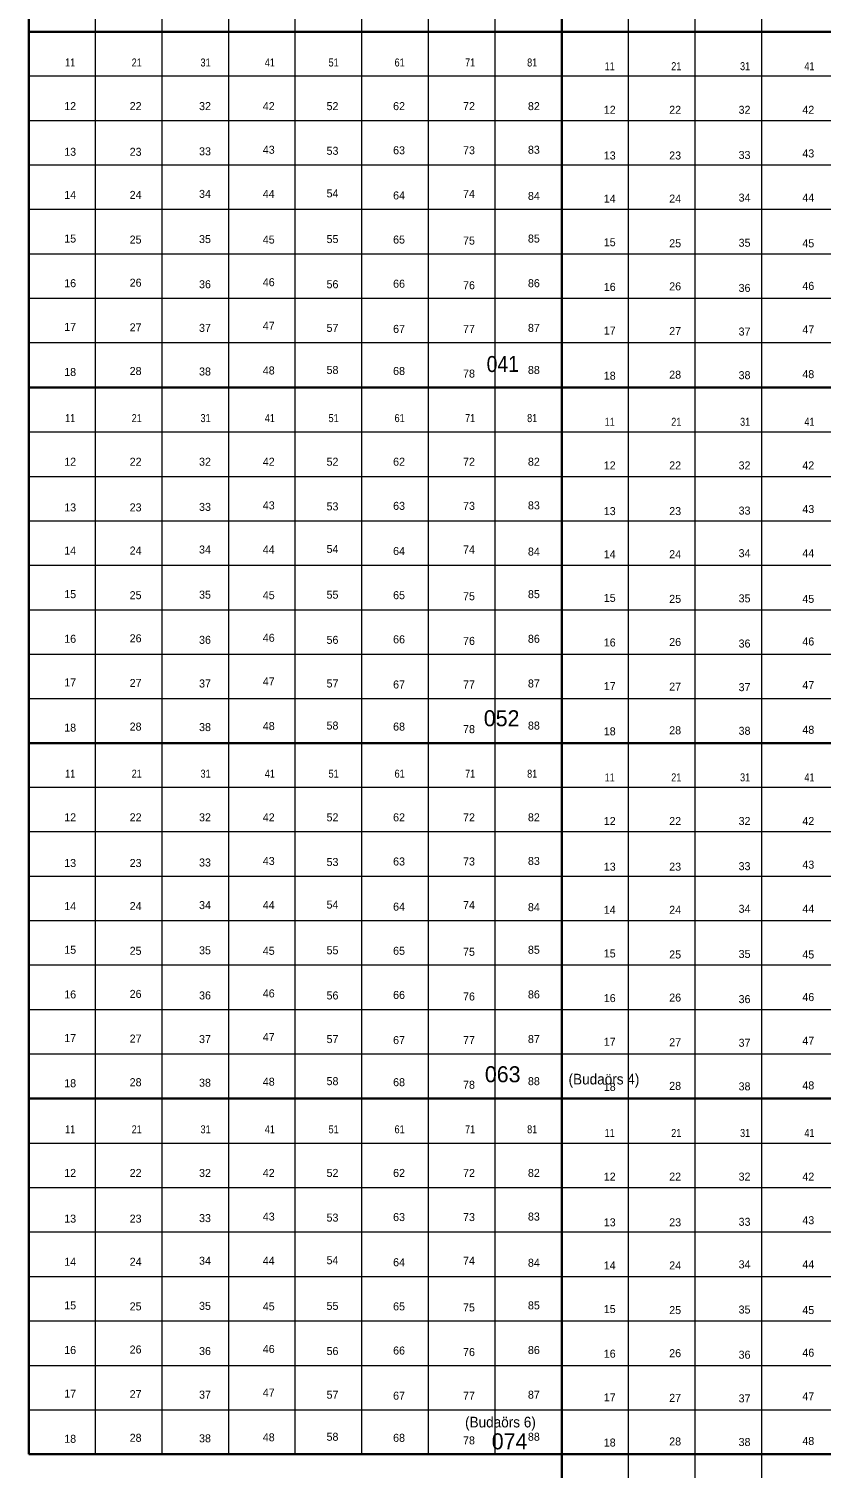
# Model space of a CAD drawing. Extents: x 639000 to 672000, y 222000 to 252000.
# Drawn here: x 639000 to 643460, y 233921 to 242017 of the extents above; entities that cross this region are included whole.
import ezdxf
from ezdxf.enums import TextEntityAlignment as Align

# ---------------------------------------------------------------- set-up
doc = ezdxf.new("R2010")
doc.units = 0
doc.header["$LTSCALE"] = 18
doc.layers.add('1', color=7, linetype='Continuous', lineweight=13)
doc.layers.add('2', color=7, linetype='Continuous')
doc.layers.add('29', color=7, linetype='Continuous')

msp = doc.modelspace()

# ---------------------------------------------------------------- linework, layer by layer
at = {"layer": '1', "lineweight": 35}
for p, q in [((639000, 234000), (639000, 248000)), ((642000, 224000), (642000, 248000)), ((639000, 242000), (672000, 242000)), ((672000, 240000), (639000, 240000)), ((639000, 238000), (672000, 238000)), ((672000, 236000), (639000, 236000)), ((639000, 234000), (672000, 234000))]:
    msp.add_line(p, q, dxfattribs=at)
at = {"layer": '1'}
for p, q in [((639375, 234000), (639375, 248000)), ((639750, 234000), (639750, 248000)), ((640125, 234000), (640125, 248000)), ((640500, 234000), (640500, 248000)), ((640875, 234000), (640875, 248000)), ((641250, 234000), (641250, 248000)), ((641625, 234000), (641625, 248000)), ((642375, 224000), (642375, 248000)), ((642750, 224000), (642750, 248000)), ((643125, 224000), (643125, 248000)), ((672000, 241750), (639000, 241750)), ((672000, 241500), (639000, 241500)), ((672000, 241250), (639000, 241250)), ((672000, 241000), (639000, 241000)), ((672000, 240750), (639000, 240750)), ((672000, 240500), (639000, 240500)), ((672000, 240250), (639000, 240250)), ((639000, 239750), (672000, 239750)), ((639000, 239500), (672000, 239500)), ((639000, 239250), (672000, 239250)), ((639000, 239000), (672000, 239000)), ((639000, 238750), (672000, 238750)), ((639000, 238500), (672000, 238500)), ((639000, 238250), (672000, 238250)), ((672000, 237750), (639000, 237750)), ((672000, 237500), (639000, 237500)), ((672000, 237250), (639000, 237250)), ((672000, 237000), (639000, 237000)), ((672000, 236750), (639000, 236750)), ((672000, 236500), (639000, 236500)), ((672000, 236250), (639000, 236250)), ((639000, 235750), (672000, 235750)), ((639000, 235500), (672000, 235500)), ((639000, 235250), (672000, 235250)), ((639000, 235000), (672000, 235000)), ((639000, 234750), (672000, 234750)), ((639000, 234500), (672000, 234500)), ((639000, 234250), (672000, 234250))]:
    msp.add_line(p, q, dxfattribs=at)

# ---------------------------------------------------------------- texts
at = {"layer": '2', "width": 0.9}
msp.add_text('041', height=90, rotation=0.36, dxfattribs=at).set_placement((641667.44, 240086.96), align=Align.CENTER)
at = {"layer": '2'}
msp.add_text('052', height=90, dxfattribs=at).set_placement((641661.02, 238094.38), align=Align.CENTER)
for s, p in [('063', (641666.99, 236092.18)), ('074', (641705.64, 234027.49))]:
    msp.add_text(s, height=90, rotation=359.94, dxfattribs=at).set_placement(p, align=Align.CENTER)
at = {"layer": '2', "width": 0.95}
for s, p in [('(Budaörs 4)', (642236.87, 236079.71)), ('(Budaörs 6)', (641654.36, 234150.79))]:
    msp.add_text(s, height=60, dxfattribs=at).set_placement(p, align=Align.CENTER)
at = {"layer": '29', "width": 0.85}
for s, p in [('11', (639232.94, 241805.06)), ('21', (639607.55, 241805.06)), ('31', (639994.85, 241805.06)), ('41', (640356.75, 241805.06)), ('51', (640715.48, 241805.06)), ('61', (641086.91, 241805.06)), ('71', (641483.74, 241805.06)), ('81', (641832.95, 241805.06)), ('11', (642269.26, 241784.35)), ('21', (642643.86, 241784.35)), ('31', (643031.16, 241784.35)), ('41', (643393.07, 241784.35)), ('11', (639232.94, 239805.06)), ('21', (639607.55, 239805.06)), ('31', (639994.85, 239805.06)), ('41', (640356.75, 239805.06)), ('51', (640715.48, 239805.06)), ('61', (641086.91, 239805.06)), ('71', (641483.74, 239805.06)), ('81', (641832.95, 239805.06)), ('11', (642269.26, 239784.35)), ('21', (642643.86, 239784.35)), ('31', (643031.16, 239784.35)), ('41', (643393.07, 239784.35)), ('11', (639232.94, 237805.06)), ('21', (639607.55, 237805.06)), ('31', (639994.85, 237805.06)), ('41', (640356.75, 237805.06)), ('51', (640715.48, 237805.06)), ('61', (641086.91, 237805.06)), ('71', (641483.74, 237805.06)), ('81', (641832.95, 237805.06)), ('11', (642269.26, 237784.35)), ('21', (642643.86, 237784.35)), ('31', (643031.16, 237784.35)), ('41', (643393.07, 237784.35)), ('11', (639232.94, 235805.06)), ('21', (639607.55, 235805.06)), ('31', (639994.85, 235805.06)), ('41', (640356.75, 235805.06)), ('51', (640715.48, 235805.06)), ('61', (641086.91, 235805.06)), ('71', (641483.74, 235805.06)), ('81', (641832.95, 235805.06)), ('11', (642269.26, 235784.35)), ('21', (642643.86, 235784.35)), ('31', (643031.16, 235784.35)), ('41', (643393.07, 235784.35))]:
    msp.add_text(s, height=45, dxfattribs=at).set_placement(p, align=Align.CENTER)
at = {"layer": '29'}
for s, p in [('12', (639232.94, 241559.67)), ('22', (639601.2, 241559.67)), ('32', (639991.67, 241559.67)), ('42', (640350.4, 241559.67)), ('52', (640709.13, 241559.67)), ('62', (641083.74, 241559.67)), ('72', (641477.39, 241559.67)), ('82', (641842.47, 241559.67)), ('12', (642269.25, 241538.96)), ('22', (642637.51, 241538.96)), ('32', (643027.99, 241538.96)), ('42', (643386.72, 241538.96)), ('13', (639232.94, 241302.73)), ('23', (639601.2, 241302.73)), ('33', (639991.67, 241305.62)), ('43', (640350.4, 241314.28)), ('53', (640709.13, 241308.51)), ('63', (641083.74, 241311.39)), ('73', (641477.39, 241311.39)), ('83', (641842.47, 241314.28)), ('43', (643386.72, 241293.57)), ('13', (642269.26, 241282.02)), ('23', (642637.51, 241282.02)), ('33', (643027.99, 241284.91)), ('14', (639232.94, 241060.23)), ('24', (639601.2, 241060.23)), ('34', (639991.67, 241066)), ('44', (640350.4, 241066)), ('54', (640709.13, 241068.89)), ('64', (641083.74, 241057.34)), ('74', (641477.39, 241066)), ('84', (641842.47, 241054.45)), ('34', (643027.99, 241045.29)), ('44', (643386.72, 241045.29)), ('14', (642269.26, 241039.52)), ('24', (642637.51, 241039.52)), ('15', (639232.94, 240814.84)), ('25', (639601.2, 240809.06)), ('35', (639991.67, 240811.95)), ('45', (640350.4, 240809.06)), ('55', (640709.13, 240811.95)), ('65', (641083.74, 240809.06)), ('75', (641477.39, 240803.29)), ('85', (641842.47, 240814.84)), ('15', (642269.26, 240794.13)), ('25', (642637.51, 240788.35)), ('35', (643027.99, 240791.24)), ('45', (643386.72, 240788.35)), ('16', (639232.94, 240563.67)), ('26', (639601.2, 240566.56)), ('36', (639991.67, 240557.9)), ('46', (640350.4, 240569.45)), ('56', (640709.13, 240557.9)), ('66', (641083.74, 240560.79)), ('86', (641842.47, 240563.67)), ('76', (641477.39, 240552.12)), ('16', (642269.26, 240542.96)), ('26', (642637.51, 240545.85)), ('36', (643027.99, 240537.19)), ('46', (643386.72, 240548.74)), ('17', (639232.94, 240318.28)), ('27', (639601.2, 240315.39)), ('47', (640350.4, 240324.05)), ('37', (639991.67, 240312.51)), ('57', (640709.13, 240312.51)), ('67', (641083.74, 240306.73)), ('77', (641477.39, 240306.73)), ('87', (641842.47, 240312.51)), ('17', (642269.26, 240297.57)), ('27', (642637.51, 240294.69)), ('37', (643027.99, 240291.8)), ('47', (643386.72, 240303.35)), ('48', (640350.4, 240072.89)), ('58', (640709.13, 240075.78)), ('88', (641842.47, 240075.78)), ('18', (639232.94, 240064.23)), ('28', (639601.2, 240070)), ('38', (639991.67, 240067.12)), ('68', (641083.74, 240070)), ('78', (641477.39, 240055.57)), ('18', (642269.25, 240043.52)), ('28', (642637.51, 240049.3)), ('38', (643027.99, 240046.41)), ('48', (643386.72, 240052.18)), ('12', (639232.94, 239559.67)), ('22', (639601.2, 239559.67)), ('32', (639991.67, 239559.67)), ('42', (640350.4, 239559.67)), ('52', (640709.13, 239559.67)), ('62', (641083.74, 239559.67)), ('72', (641477.39, 239559.67)), ('82', (641842.47, 239559.67)), ('12', (642269.25, 239538.96)), ('22', (642637.51, 239538.96)), ('32', (643027.99, 239538.96)), ('42', (643386.72, 239538.96)), ('13', (639232.94, 239302.73)), ('23', (639601.2, 239302.73)), ('33', (639991.67, 239305.62)), ('43', (640350.4, 239314.28)), ('53', (640709.13, 239308.51)), ('63', (641083.74, 239311.39)), ('73', (641477.39, 239311.39)), ('83', (641842.47, 239314.28)), ('13', (642269.26, 239282.02)), ('23', (642637.51, 239282.02)), ('33', (643027.99, 239284.91)), ('43', (643386.72, 239293.57)), ('14', (639232.94, 239060.23)), ('24', (639601.2, 239060.23)), ('34', (639991.67, 239066)), ('44', (640350.4, 239066)), ('54', (640709.13, 239068.89)), ('64', (641083.74, 239057.34)), ('74', (641477.39, 239066)), ('84', (641842.47, 239054.45)), ('14', (642269.26, 239039.52)), ('24', (642637.51, 239039.52)), ('34', (643027.99, 239045.29)), ('44', (643386.72, 239045.29)), ('15', (639232.94, 238814.84)), ('25', (639601.2, 238809.06)), ('35', (639991.67, 238811.95)), ('45', (640350.4, 238809.06)), ('55', (640709.13, 238811.95)), ('65', (641083.74, 238809.06)), ('75', (641477.39, 238803.29)), ('85', (641842.47, 238814.84)), ('15', (642269.26, 238794.13)), ('25', (642637.51, 238788.35)), ('35', (643027.99, 238791.24)), ('45', (643386.72, 238788.35)), ('16', (639232.94, 238563.67)), ('26', (639601.2, 238566.56)), ('36', (639991.67, 238557.9)), ('46', (640350.4, 238569.45)), ('56', (640709.13, 238557.9)), ('66', (641083.74, 238560.79)), ('76', (641477.39, 238552.12)), ('86', (641842.47, 238563.67)), ('16', (642269.26, 238542.96)), ('26', (642637.51, 238545.85)), ('36', (643027.99, 238537.19)), ('46', (643386.72, 238548.74)), ('17', (639232.94, 238318.28)), ('27', (639601.2, 238315.39)), ('37', (639991.67, 238312.51)), ('47', (640350.4, 238324.05)), ('57', (640709.13, 238312.51)), ('67', (641083.74, 238306.73)), ('77', (641477.39, 238306.73)), ('87', (641842.47, 238312.51)), ('17', (642269.26, 238297.57)), ('27', (642637.51, 238294.69)), ('37', (643027.99, 238291.8)), ('47', (643386.72, 238303.35)), ('18', (639232.94, 238064.23)), ('28', (639601.2, 238070)), ('38', (639991.67, 238067.12)), ('48', (640350.4, 238072.89)), ('58', (640709.13, 238075.78)), ('68', (641083.74, 238070)), ('78', (641477.39, 238055.57)), ('88', (641842.47, 238075.78)), ('28', (642637.51, 238049.3)), ('48', (643386.72, 238052.18)), ('18', (642269.25, 238043.52)), ('38', (643027.99, 238046.41)), ('12', (639232.94, 237559.67)), ('22', (639601.2, 237559.67)), ('32', (639991.67, 237559.67)), ('42', (640350.4, 237559.67)), ('52', (640709.13, 237559.67)), ('62', (641083.74, 237559.67)), ('72', (641477.39, 237559.67)), ('82', (641842.47, 237559.67)), ('12', (642269.25, 237538.96)), ('22', (642637.51, 237538.96)), ('32', (643027.99, 237538.96)), ('42', (643386.72, 237538.96)), ('13', (639232.94, 237302.73)), ('23', (639601.2, 237302.73)), ('33', (639991.67, 237305.62)), ('43', (640350.4, 237314.28)), ('53', (640709.13, 237308.51)), ('63', (641083.74, 237311.39)), ('73', (641477.39, 237311.39)), ('83', (641842.47, 237314.28)), ('13', (642269.26, 237282.02)), ('23', (642637.51, 237282.02)), ('33', (643027.99, 237284.91)), ('43', (643386.72, 237293.57)), ('14', (639232.94, 237060.23)), ('24', (639601.2, 237060.23)), ('34', (639991.67, 237066)), ('44', (640350.4, 237066)), ('54', (640709.13, 237068.89)), ('64', (641083.74, 237057.34)), ('74', (641477.39, 237066)), ('84', (641842.47, 237054.45)), ('14', (642269.26, 237039.52)), ('24', (642637.51, 237039.52)), ('34', (643027.99, 237045.29)), ('44', (643386.72, 237045.29)), ('15', (639232.94, 236814.84)), ('25', (639601.2, 236809.06)), ('35', (639991.67, 236811.95)), ('45', (640350.4, 236809.06)), ('55', (640709.13, 236811.95)), ('65', (641083.74, 236809.06)), ('75', (641477.39, 236803.29)), ('85', (641842.47, 236814.84)), ('15', (642269.26, 236794.13)), ('25', (642637.51, 236788.35)), ('35', (643027.99, 236791.24)), ('45', (643386.72, 236788.35)), ('16', (639232.94, 236563.67)), ('26', (639601.2, 236566.56)), ('36', (639991.67, 236557.9)), ('46', (640350.4, 236569.45)), ('56', (640709.13, 236557.9)), ('66', (641083.74, 236560.79)), ('76', (641477.39, 236552.12)), ('86', (641842.47, 236563.67)), ('16', (642269.26, 236542.96)), ('26', (642637.51, 236545.85)), ('36', (643027.99, 236537.19)), ('46', (643386.72, 236548.74)), ('17', (639232.94, 236318.28)), ('27', (639601.2, 236315.39)), ('37', (639991.67, 236312.51)), ('47', (640350.4, 236324.05)), ('57', (640709.13, 236312.51)), ('67', (641083.74, 236306.73)), ('77', (641477.39, 236306.73)), ('87', (641842.47, 236312.51)), ('17', (642269.26, 236297.57)), ('27', (642637.51, 236294.69)), ('37', (643027.99, 236291.8)), ('47', (643386.72, 236303.35)), ('18', (639232.94, 236064.23)), ('28', (639601.2, 236070)), ('38', (639991.67, 236067.12)), ('48', (640350.4, 236072.89)), ('58', (640709.13, 236075.78)), ('68', (641083.74, 236070)), ('78', (641477.39, 236055.57)), ('88', (641842.47, 236075.78)), ('18', (642269.25, 236043.52)), ('28', (642637.51, 236049.3)), ('38', (643027.99, 236046.41)), ('48', (643386.72, 236052.18)), ('12', (639232.94, 235559.67)), ('22', (639601.2, 235559.67)), ('32', (639991.67, 235559.67)), ('42', (640350.4, 235559.67)), ('52', (640709.13, 235559.67)), ('62', (641083.74, 235559.67)), ('72', (641477.39, 235559.67)), ('82', (641842.47, 235559.67)), ('12', (642269.25, 235538.96)), ('22', (642637.51, 235538.96)), ('32', (643027.99, 235538.96)), ('42', (643386.72, 235538.96)), ('13', (639232.94, 235302.73)), ('23', (639601.2, 235302.73)), ('33', (639991.67, 235305.62)), ('43', (640350.4, 235314.28)), ('53', (640709.13, 235308.51)), ('63', (641083.74, 235311.39)), ('73', (641477.39, 235311.39)), ('83', (641842.47, 235314.28)), ('13', (642269.26, 235282.02)), ('23', (642637.51, 235282.02)), ('33', (643027.99, 235284.91)), ('43', (643386.72, 235293.57)), ('14', (639232.94, 235060.23)), ('24', (639601.2, 235060.23)), ('34', (639991.67, 235066)), ('44', (640350.4, 235066)), ('54', (640709.13, 235068.89)), ('64', (641083.74, 235057.34)), ('74', (641477.39, 235066)), ('84', (641842.47, 235054.45)), ('14', (642269.26, 235039.52)), ('24', (642637.51, 235039.52)), ('34', (643027.99, 235045.29)), ('44', (643386.72, 235045.29)), ('15', (639232.94, 234814.84)), ('35', (639991.67, 234811.95)), ('55', (640709.13, 234811.95)), ('85', (641842.47, 234814.84)), ('25', (639601.2, 234809.06)), ('45', (640350.4, 234809.06)), ('65', (641083.74, 234809.06)), ('75', (641477.39, 234803.29)), ('15', (642269.26, 234794.13)), ('25', (642637.51, 234788.35)), ('35', (643027.99, 234791.24)), ('45', (643386.72, 234788.35)), ('46', (640350.4, 234569.45)), ('16', (639232.94, 234563.67)), ('26', (639601.2, 234566.56)), ('36', (639991.67, 234557.9)), ('56', (640709.13, 234557.9)), ('66', (641083.74, 234560.79)), ('76', (641477.39, 234552.12)), ('86', (641842.47, 234563.67)), ('16', (642269.26, 234542.96)), ('26', (642637.51, 234545.85)), ('36', (643027.99, 234537.19)), ('46', (643386.72, 234548.74)), ('17', (639232.94, 234318.28)), ('27', (639601.2, 234315.39)), ('37', (639991.67, 234312.51)), ('47', (640350.4, 234324.05)), ('57', (640709.13, 234312.51)), ('67', (641083.74, 234306.73)), ('77', (641477.39, 234306.73)), ('87', (641842.47, 234312.51)), ('17', (642269.26, 234297.57)), ('27', (642637.51, 234294.69)), ('37', (643027.99, 234291.8)), ('47', (643386.72, 234303.35)), ('18', (639232.94, 234064.23)), ('28', (639601.2, 234070)), ('38', (639991.67, 234067.12)), ('48', (640350.4, 234072.89)), ('58', (640709.13, 234075.78)), ('68', (641083.74, 234070)), ('78', (641477.39, 234055.57)), ('88', (641842.47, 234075.78)), ('18', (642269.25, 234043.52)), ('28', (642637.51, 234049.3)), ('38', (643027.99, 234046.41)), ('48', (643386.72, 234052.18))]:
    msp.add_text(s, height=45, dxfattribs=at).set_placement(p, align=Align.CENTER)

doc.saveas('drawing.dxf')
